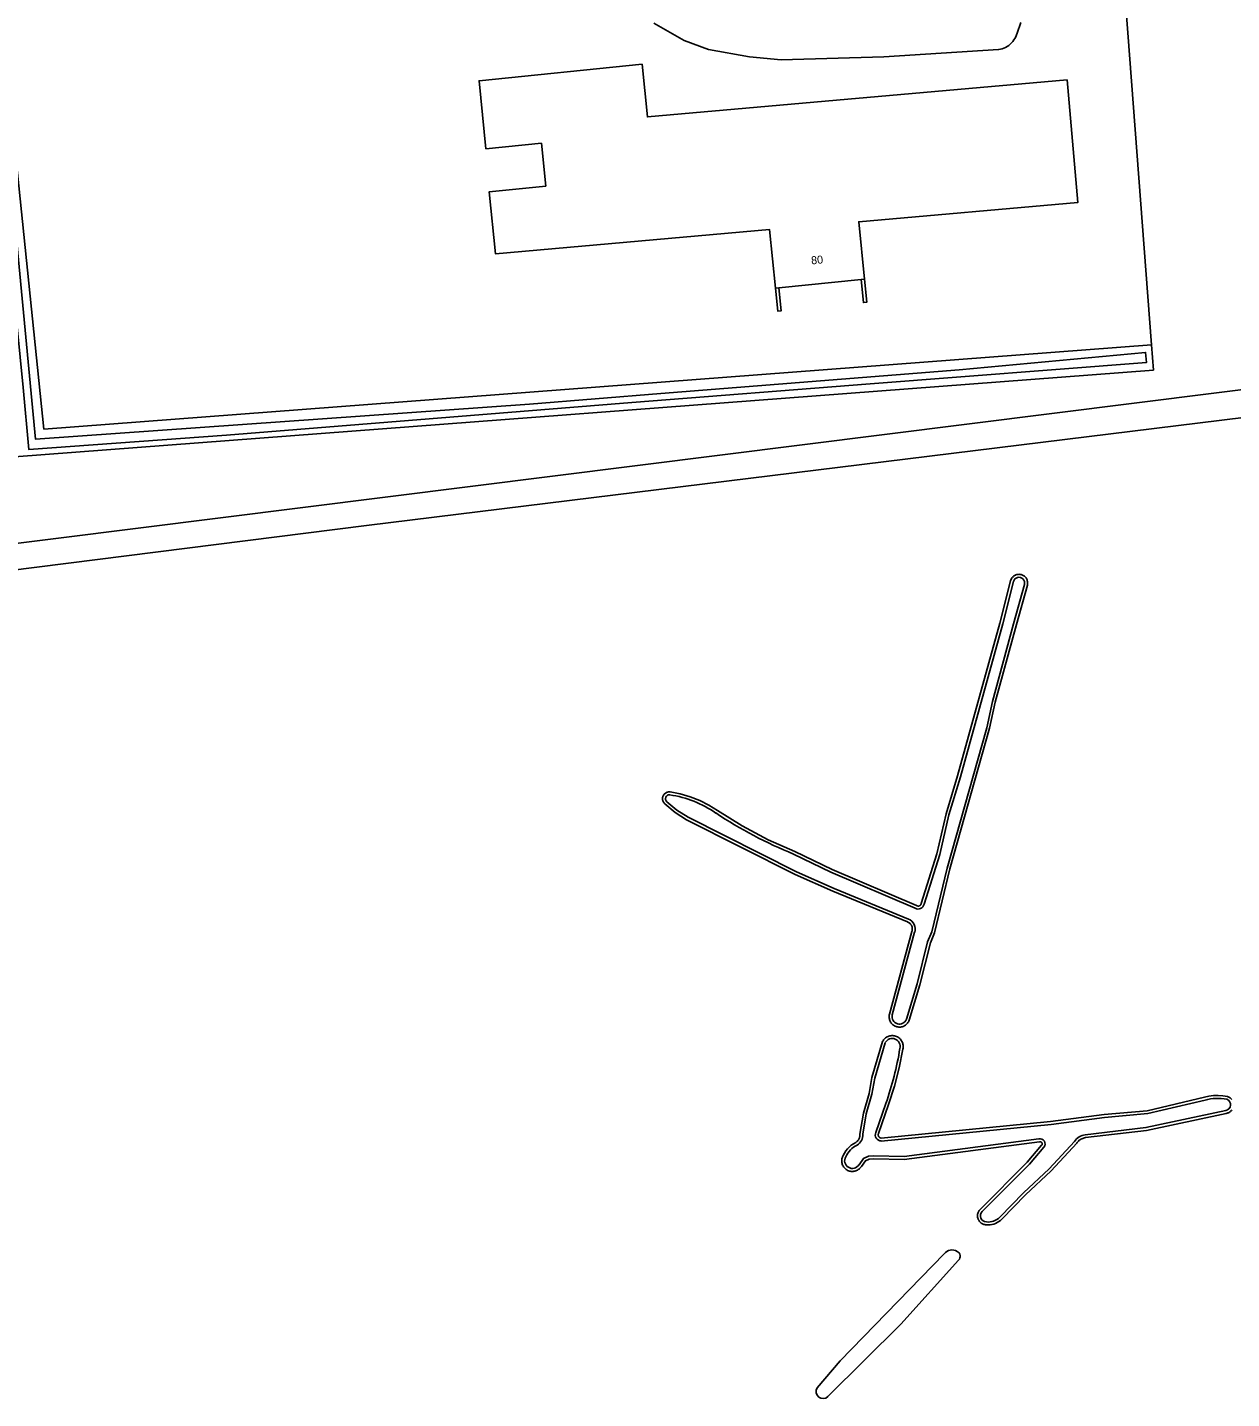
# Model space of a CAD drawing. Extents: x 158132 to 159658, y 385257 to 387209.
# Drawn here: x 158558.9 to 158709.3, y 386403.2 to 386574.5 of the extents above; entities that cross this region are included whole.
import ezdxf

# ---------------------------------------------------------------- set-up
doc = ezdxf.new("R2010")
doc.units = 0
for name, color, linetype in [('IMGEO_Gemengd_bos', 7, 'Continuous'), ('IMGEO_Groenvoorziening', 7, 'Continuous'), ('IMGEO_Muur', 7, 'Continuous'), ('IMGEO_Pand', 7, 'Continuous'), ('IMGEO_Pand_nummerreeks', 7, 'Continuous'), ('IMGEO_Rijbaan_lokaal_gesloten', 7, 'Continuous'), ('IMGEO_Waterloop', 7, 'Continuous')]:
    doc.layers.add(name, color=color, linetype=linetype)

msp = doc.modelspace()

# ---------------------------------------------------------------- linework, layer by layer
at = {"layer": 'IMGEO_Gemengd_bos'}
for points in [[(158699.27, 386534.87), (158694.75, 386594.73)], [(158699.27, 386534.87), (158699.52, 386531.69), (158557.25, 386520.85), (158552.81, 386577.12), (158552.39, 386582.4), (158552.53, 386582.41)], [(158641.2, 386475.53), (158654.78, 386468.68), (158659.49, 386466.59), (158668.78, 386462.77), (158668.86, 386462.74), (158668.93, 386462.71), (158669, 386462.66), (158669.06, 386462.61), (158669.12, 386462.56), (158669.18, 386462.5), (158669.23, 386462.44), (158669.28, 386462.37), (158669.31, 386462.3), (158669.35, 386462.22), (158669.37, 386462.14), (158669.39, 386462.06), (158669.4, 386461.98), (158669.4, 386461.9), (158669.4, 386461.82), (158669.39, 386461.74), (158669.37, 386461.66), (158669.35, 386461.58), (158666.55, 386451.23), (158666.52, 386451.12), (158666.51, 386451.01), (158666.51, 386450.9), (158666.52, 386450.79), (158666.53, 386450.68), (158666.56, 386450.57), (158666.6, 386450.46), (158666.64, 386450.36), (158666.69, 386450.26), (158666.76, 386450.17), (158666.82, 386450.08), (158666.9, 386450), (158666.98, 386449.93), (158667.07, 386449.86), (158667.17, 386449.8), (158667.27, 386449.75), (158667.37, 386449.71), (158667.48, 386449.68), (158667.59, 386449.66), (158667.7, 386449.64), (158667.81, 386449.64), (158667.92, 386449.64), (158668.03, 386449.66), (158668.14, 386449.68), (158668.24, 386449.72), (158668.35, 386449.76), (158668.45, 386449.81), (158668.54, 386449.87), (158668.63, 386449.94), (158668.71, 386450.02), (158668.79, 386450.1), (158668.85, 386450.19), (158668.91, 386450.28), (158668.96, 386450.38), (158669.01, 386450.48), (158670.35, 386454.92), (158671.66, 386460.17), (158672.17, 386461.41), (158674.1, 386469.41), (158679.06, 386486.95), (158679.76, 386490.22), (158682.41, 386499.9), (158683.77, 386504.83), (158683.79, 386504.93), (158683.8, 386505.02), (158683.8, 386505.11), (158683.8, 386505.21), (158683.79, 386505.3), (158683.76, 386505.39), (158683.74, 386505.48), (158683.7, 386505.57), (158683.66, 386505.65), (158683.61, 386505.73), (158683.55, 386505.81), (158683.48, 386505.88), (158683.42, 386505.94), (158683.34, 386506), (158683.26, 386506.05), (158683.18, 386506.09), (158683.09, 386506.12), (158683, 386506.15), (158682.91, 386506.17), (158682.82, 386506.18), (158682.72, 386506.19), (158682.63, 386506.18), (158682.53, 386506.17), (158682.44, 386506.15), (158682.35, 386506.12), (158682.27, 386506.09), (158682.18, 386506.04), (158682.1, 386505.99), (158682.03, 386505.93), (158681.96, 386505.87), (158681.9, 386505.8), (158681.84, 386505.73), (158681.79, 386505.65), (158681.75, 386505.56), (158681.71, 386505.48), (158681.68, 386505.39), (158680.35, 386500.09), (158675.06, 386481), (158673.61, 386476.25), (158672.48, 386471.28), (158670.5, 386465.06), (158670.5, 386465.03), (158670.49, 386465), (158670.48, 386464.97), (158670.46, 386464.94), (158670.45, 386464.91), (158670.43, 386464.88), (158670.4, 386464.86), (158670.38, 386464.84), (158670.36, 386464.82), (158670.33, 386464.8), (158670.3, 386464.78), (158670.27, 386464.77), (158670.24, 386464.76), (158670.21, 386464.75), (158670.17, 386464.75), (158670.14, 386464.74), (158670.11, 386464.75), (158670.08, 386464.75), (158670.04, 386464.76), (158670.01, 386464.77), (158669.98, 386464.78), (158669.95, 386464.79), (158669.93, 386464.81), (158659.38, 386469.3), (158654.72, 386471.57), (158651.39, 386473.04), (158648.16, 386474.75), (158645.07, 386476.67), (158643.98, 386477.35), (158642.84, 386477.93), (158641.64, 386478.4), (158640.41, 386478.76), (158639.15, 386479), (158639.08, 386479.01), (158639, 386479.01), (158638.92, 386479), (158638.85, 386478.99), (158638.78, 386478.97), (158638.71, 386478.94), (158638.64, 386478.91), (158638.58, 386478.87), (158638.52, 386478.82), (158638.46, 386478.77), (158638.41, 386478.72), (158638.36, 386478.66), (158638.32, 386478.6), (158638.28, 386478.53), (158638.25, 386478.46), (158638.23, 386478.39), (158638.21, 386478.32), (158638.2, 386478.24), (158638.2, 386478.16), (158638.2, 386478.09), (158638.21, 386478.02), (158638.22, 386477.94), (158638.25, 386477.87), (158638.27, 386477.8), (158638.31, 386477.73), (158638.35, 386477.67), (158638.39, 386477.61), (158638.45, 386477.55), (158638.5, 386477.5), (158639.77, 386476.42), (158641.2, 386475.53)], [(158709.3, 386440.58), (158709.24, 386440.65), (158709.18, 386440.72), (158709.1, 386440.78), (158709.03, 386440.84), (158708.94, 386440.89), (158708.86, 386440.93), (158708.77, 386440.97), (158708.19, 386441.06), (158707.61, 386441.09), (158707.03, 386441.07), (158706.45, 386440.99), (158705.88, 386440.87), (158698.75, 386439.18), (158693.37, 386438.71), (158686.68, 386437.82), (158665.5, 386435.77), (158665.47, 386435.77), (158665.43, 386435.78), (158665.4, 386435.79), (158665.36, 386435.81), (158665.33, 386435.82), (158665.3, 386435.84), (158665.28, 386435.87), (158665.25, 386435.89), (158665.23, 386435.92), (158665.21, 386435.95), (158665.19, 386435.98), (158665.17, 386436.01), (158665.16, 386436.04), (158665.15, 386436.08), (158665.15, 386436.11), (158665.14, 386436.15), (158665.14, 386436.18), (158665.15, 386436.22), (158665.15, 386436.26), (158665.16, 386436.29), (158665.17, 386436.32), (158666.44, 386439.97), (158667.17, 386442.24), (158667.76, 386444.54), (158668.21, 386446.88), (158668.24, 386447), (158668.25, 386447.12), (158668.25, 386447.24), (158668.24, 386447.36), (158668.23, 386447.48), (158668.2, 386447.59), (158668.16, 386447.71), (158668.11, 386447.82), (158668.05, 386447.92), (158667.98, 386448.02), (158667.91, 386448.11), (158667.82, 386448.2), (158667.73, 386448.28), (158667.63, 386448.35), (158667.53, 386448.41), (158667.42, 386448.46), (158667.31, 386448.5), (158667.19, 386448.53), (158667.08, 386448.55), (158666.96, 386448.57), (158666.84, 386448.57), (158666.72, 386448.55), (158666.6, 386448.53), (158666.48, 386448.5), (158666.37, 386448.46), (158666.26, 386448.41), (158666.16, 386448.35), (158666.06, 386448.28), (158665.97, 386448.2), (158665.88, 386448.12), (158665.81, 386448.03), (158665.74, 386447.93), (158665.68, 386447.82), (158664.36, 386443.34), (158663.99, 386441.35), (158663.29, 386438.89), (158662.85, 386436.26), (158662.85, 386436.16), (158662.85, 386436.07), (158662.83, 386435.98), (158662.81, 386435.88), (158662.79, 386435.79), (158662.75, 386435.71), (158662.71, 386435.62), (158662.66, 386435.54), (158662.61, 386435.47), (158662.54, 386435.4), (158662.48, 386435.33), (158662.4, 386435.27), (158662.33, 386435.22), (158662.04, 386435.05), (158661.78, 386434.86), (158661.53, 386434.65), (158661.3, 386434.41), (158661.1, 386434.16), (158660.91, 386433.89), (158660.76, 386433.6), (158660.7, 386433.5), (158660.66, 386433.39), (158660.62, 386433.29), (158660.6, 386433.17), (158660.58, 386433.06), (158660.58, 386432.94), (158660.58, 386432.83), (158660.59, 386432.71), (158660.62, 386432.6), (158660.65, 386432.49), (158660.69, 386432.38), (158660.75, 386432.28), (158660.81, 386432.18), (158660.88, 386432.09), (158660.95, 386432), (158661.04, 386431.92), (158661.13, 386431.85), (158661.22, 386431.79), (158661.32, 386431.73), (158661.43, 386431.69), (158661.54, 386431.65), (158661.65, 386431.62), (158661.77, 386431.61), (158661.88, 386431.6), (158662, 386431.6), (158662.11, 386431.62), (158662.22, 386431.64), (158662.33, 386431.67), (158662.44, 386431.71), (158662.55, 386431.76), (158662.64, 386431.82), (158662.74, 386431.89), (158662.82, 386431.97), (158662.9, 386432.05), (158662.98, 386432.14), (158663.04, 386432.23), (158663.54, 386432.94), (158664.01, 386433.14), (158664.61, 386433.18)], [(158664.61, 386433.18), (158668.39, 386433.1), (158685.27, 386435.3), (158685.29, 386435.3), (158685.31, 386435.31), (158685.34, 386435.31), (158685.36, 386435.31), (158685.38, 386435.31), (158685.41, 386435.3), (158685.43, 386435.3), (158685.45, 386435.29), (158685.47, 386435.28), (158685.49, 386435.27), (158685.51, 386435.26), (158685.53, 386435.24), (158685.55, 386435.23), (158685.56, 386435.21), (158685.58, 386435.19), (158685.59, 386435.17), (158685.6, 386435.15), (158685.61, 386435.12), (158685.61, 386435.1), (158685.62, 386435.08), (158685.62, 386435.05), (158685.62, 386435.03), (158685.62, 386435.01), (158685.62, 386434.98), (158685.61, 386434.96), (158685.6, 386434.94), (158685.59, 386434.92), (158685.58, 386434.9), (158685.57, 386434.88), (158685.55, 386434.86), (158683.75, 386432.74), (158677.88, 386426.85), (158677.81, 386426.78), (158677.75, 386426.71), (158677.7, 386426.62), (158677.65, 386426.54), (158677.62, 386426.45), (158677.59, 386426.35), (158677.56, 386426.26), (158677.55, 386426.16), (158677.54, 386426.07), (158677.55, 386425.97), (158677.56, 386425.87), (158677.58, 386425.78), (158677.61, 386425.68), (158677.64, 386425.59), (158677.69, 386425.51), (158677.74, 386425.42), (158677.8, 386425.34), (158677.86, 386425.27), (158677.93, 386425.2), (158678.01, 386425.14), (158678.09, 386425.09), (158678.17, 386425.04), (158678.26, 386425), (158678.35, 386424.97), (158678.45, 386424.95), (158678.55, 386424.93), (158678.64, 386424.92), (158678.88, 386424.92), (158679.11, 386424.93), (158679.35, 386424.97), (158679.58, 386425.03), (158679.8, 386425.11), (158680.02, 386425.21), (158680.22, 386425.33), (158680.42, 386425.46), (158680.6, 386425.62), (158683.55, 386428.68), (158686.75, 386431.66), (158689.95, 386435.11), (158690.01, 386435.22), (158690.09, 386435.31), (158690.17, 386435.4), (158690.26, 386435.49), (158690.36, 386435.56), (158690.46, 386435.63), (158690.57, 386435.69), (158690.68, 386435.73), (158690.8, 386435.77), (158690.92, 386435.8), (158691.04, 386435.82), (158698.64, 386436.72), (158708.62, 386438.84), (158708.71, 386438.87), (158708.8, 386438.9), (158708.89, 386438.93), (158708.98, 386438.98), (158709.06, 386439.03), (158709.13, 386439.09), (158709.2, 386439.16), (158709.27, 386439.23), (158709.32, 386439.31)]]:
    msp.add_lwpolyline(points, dxfattribs=at)
at = {"layer": 'IMGEO_Groenvoorziening'}
msp.add_lwpolyline([(158552.53, 386582.41), (158554.97, 386582.61), (158555.4, 386577.39), (158560.93, 386524.32), (158699.27, 386534.87)], dxfattribs=at)
at = {"layer": 'IMGEO_Muur'}
for points in [[(158663.44, 386543.07), (158663.73, 386540.19), (158663.3, 386540.14), (158663.01, 386543.03)], [(158652.72, 386541.99), (158653.02, 386539.1), (158652.59, 386539.06), (158652.3, 386541.95)]]:
    msp.add_lwpolyline(points, dxfattribs=at)
at = {"layer": 'IMGEO_Pand'}
for points in [[(158652.3, 386541.95), (158651.56, 386549.25), (158617.33, 386546.23), (158616.55, 386553.98), (158623.61, 386554.69), (158623.07, 386560.04), (158616.14, 386559.34), (158615.28, 386567.83), (158635.64, 386569.9), (158636.3, 386563.33), (158688.73, 386567.95), (158690.08, 386552.65), (158662.71, 386550.23), (158663.44, 386543.07)], [(158663.01, 386543.03), (158652.72, 386541.99)], [(158663.44, 386543.07), (158663.01, 386543.03)], [(158652.72, 386541.99), (158652.3, 386541.95)]]:
    msp.add_lwpolyline(points, dxfattribs=at)
at = {"layer": 'IMGEO_Rijbaan_lokaal_gesloten'}
for points in [[(158682.94, 386575.1), (158682.48, 386573.78), (158682.41, 386573.56), (158682.32, 386573.34), (158682.22, 386573.13), (158682.1, 386572.93), (158681.96, 386572.74), (158681.8, 386572.57), (158681.64, 386572.41), (158681.46, 386572.26), (158681.26, 386572.13), (158681.06, 386572.01), (158680.84, 386571.91), (158680.62, 386571.84), (158680.4, 386571.78), (158680.17, 386571.74), (158665.83, 386570.82), (158653, 386570.44), (158649.07, 386570.81), (158643.94, 386571.76), (158640.88, 386572.86), (158637.09, 386575.02)], [(158406.58, 386559.5), (158407.36, 386554.43), (158412.58, 386546.23), (158416.91, 386541.17), (158442.58, 386509.71), (158448.36, 386503.02), (158452.61, 386500), (158453.96, 386499.04), (158456.49, 386498.14), (158462.82, 386498.14), (158466.25, 386498.5), (158477.43, 386500), (158500, 386502.83), (158738.6, 386532.78), (158740.9, 386533.67)], [(158725.35, 386527.57), (158724.95, 386527.52), (158601.22, 386512.28), (158504.01, 386500), (158500, 386499.49), (158489.2, 386498.32), (158473.3, 386495.97), (158467.81, 386495.38), (158464.4, 386494.85)]]:
    msp.add_lwpolyline(points, dxfattribs=at)
at = {"layer": 'IMGEO_Waterloop'}
for points in [[(158553.1, 386581.98), (158554.24, 386582.06), (158554.54, 386578.89), (158559.85, 386523.08), (158621.58, 386527.43), (158638, 386528.76), (158675.25, 386531.75), (158698.53, 386533.91), (158698.65, 386532.63), (158664.15, 386529.97), (158634.37, 386527.66), (158583.72, 386523.55), (158559.05, 386521.76), (158558.32, 386529.53), (158553.17, 386581.3), (158553.1, 386581.98)], [(158683.41, 386504.93), (158682.06, 386500), (158679.41, 386490.31), (158678.71, 386487.03), (158673.74, 386469.5), (158671.82, 386461.52), (158671.31, 386460.28), (158670, 386455.02), (158668.66, 386450.6)], [(158670.86, 386464.97), (158672.84, 386471.18), (158673.96, 386476.15), (158675.41, 386480.9), (158680.7, 386500), (158682.04, 386505.29)], [(158659.64, 386466.93), (158654.93, 386469.01), (158641.38, 386475.85), (158639.99, 386476.72), (158638.74, 386477.78)], [(158654.57, 386471.23), (158659.23, 386468.97), (158669.75, 386464.49)], [(158668.91, 386463.11), (158659.64, 386466.93)], [(158666.9, 386451.14), (158669.69, 386461.47)], [(158663.21, 386436.24), (158663.65, 386438.81), (158664.34, 386441.26), (158664.71, 386443.26), (158666.02, 386447.68)], [(158666.1, 386440.09), (158664.83, 386436.45)], [(158665.51, 386435.4), (158686.73, 386437.45), (158693.41, 386438.35), (158698.81, 386438.82), (158705.97, 386440.51)], [(158708.55, 386439.2), (158698.58, 386437.08), (158691, 386436.18)], [(158685.19, 386435.66), (158668.37, 386433.46)], [(158678.14, 386426.59), (158684.02, 386432.49), (158685.83, 386434.62)], [(158689.65, 386435.34), (158686.49, 386431.92), (158683.3, 386428.94), (158680.34, 386425.88)], [(158668.37, 386433.46), (158664.6, 386433.55), (158663.92, 386433.5), (158663.3, 386433.23), (158662.74, 386432.43)], [(158673.38, 386421.3), (158660.39, 386407.93), (158657.51, 386404.56)], [(158658.86, 386403.47), (158667.97, 386412.51), (158675.17, 386420.52)]]:
    msp.add_lwpolyline(points, dxfattribs=at)
for centre, radius, start, end in [((158682.72, 386505.11), 0.71, 345.0348, 165.1906), ((158639.05, 386478.16), 0.486, 83.6938, 230.1674), ((158637.12, 386465.16), 13.62, 55.3439, 81.6235), ((158674.09, 386519.86), 52.39, 236.1026, 248.1294), ((158670.14, 386465.11), 0.735, 238.1675, 348.9882), ((158668.48, 386461.9), 1.29, 340.3495, 70.615), ((158667.8, 386450.93), 0.922, 166.6904, 339.3742), ((158666.89, 386447.21), 0.995, 345.4178, 151.3028), ((158628.33, 386453.44), 40.05, 340.5412, 350.688), ((158707.55, 386434.73), 5.99, 79.1876, 105.2257), ((158708.41, 386439.93), 0.738, 280.859, 69.1176), ((158661.74, 386436.16), 1.48, 301.3461, 2.9853), ((158665.54, 386436.17), 0.766, 157.9456, 267.3763), ((158691.19, 386434.39), 1.8, 95.9259, 148.2986), ((158664.02, 386432), 3.27, 117.6138, 154.0869), ((158685.35, 386435.04), 0.638, 318.6696, 104.2742), ((158661.91, 386432.94), 0.966, 149.5884, 328.4637), ((158678.67, 386426.05), 0.762, 134.6535, 268.9797), ((158678.82, 386427.52), 2.24, 265.8594, 312.7389), ((158674.37, 386420.54), 1.25, 59.6183, 142.525), ((158674.73, 386421.01), 0.664, 311.9567, 65.919), ((158658.26, 386404.1), 0.876, 148.7388, 313.653)]:
    msp.add_arc(centre, radius, start, end, dxfattribs=at)

# ---------------------------------------------------------------- texts
at = {"layer": 'IMGEO_Pand_nummerreeks'}
msp.add_text('80', height=1, rotation=5.5176, dxfattribs=at).set_placement((158656.81, 386544.89))

doc.saveas('drawing.dxf')
